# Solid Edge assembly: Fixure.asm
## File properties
Author: CADCIM
Template: NORMENG.ASM
Last saved by: CADCIM
Revision: 1
Application: Solid Edge
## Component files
Nut.par
End Plate.par
Disk.par
support pin.par
Spacer.par
Part9.par
bolt.par
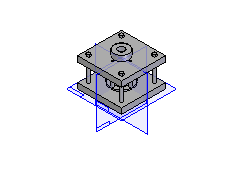
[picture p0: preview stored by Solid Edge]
